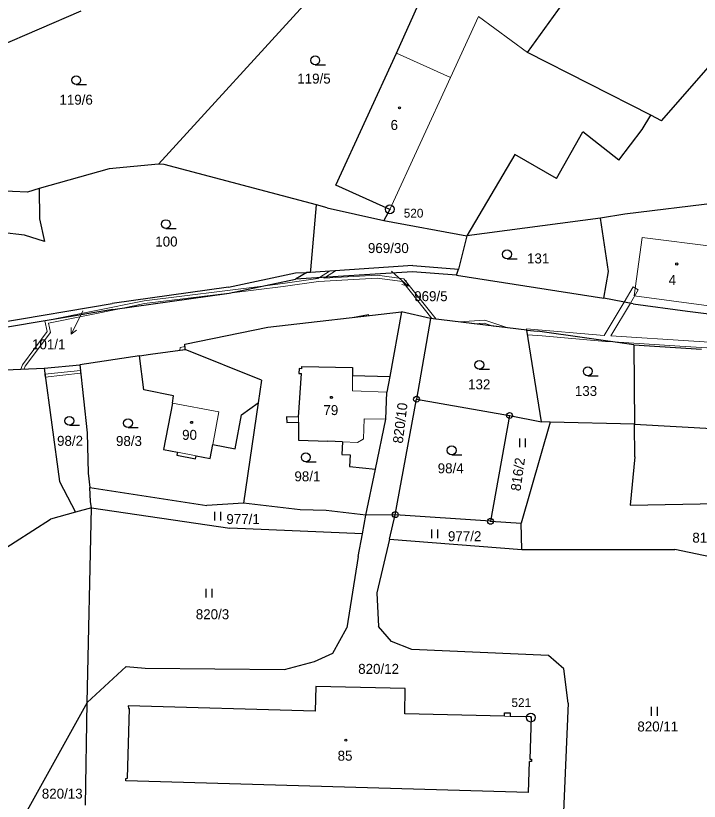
# Model space of a CAD drawing. Extents: x -754970 to -752637, y -970569 to -968179.
# Drawn here: x -752908.8 to -752792.3, y -969522.6 to -969388.8 of the extents above; entities that cross this region are included whole.
import ezdxf
from ezdxf.enums import TextEntityAlignment as Align

# ---------------------------------------------------------------- set-up
doc = ezdxf.new("R2010")
doc.units = 0
doc.header["$LTSCALE"] = 0.68
for name, color, linetype, lineweight in [('1', 7, 'Continuous', 25), ('13', 7, 'Continuous', 13), ('3', 7, 'Continuous', 25), ('4', 7, 'Continuous', 13), ('5', 7, 'Continuous', 25), ('7', 7, 'Continuous', 13), ('8', 7, 'Continuous', 25)]:
    doc.layers.add(name, color=color, linetype=linetype, lineweight=lineweight)
doc.layers.add('2', color=7, linetype='Continuous')

msp = doc.modelspace()

# ---------------------------------------------------------------- linework, layer by layer
at = {"layer": '1'}
for p, q in [((-752884.46, -969414.09), (-752849.18, -969375.41)), ((-752798.77, -969406.66), (-752773.21, -969377.55)), ((-752843.92, -969395.16), (-752838.37, -969382.79)), ((-752821.57, -969395.02), (-752815.7, -969386.84)), ((-752897.67, -969387.98), (-752916.6, -969396.15)), ((-752800.58, -969405.74), (-752821.57, -969395.02)), ((-752854.25, -969417.65), (-752843.92, -969395.16)), ((-752802.06, -969408.16), (-752800.58, -969405.74)), ((-752798.77, -969406.66), (-752800.58, -969405.74)), ((-752806.02, -969413.38), (-752802.06, -969408.16)), ((-752816.62, -969416.52), (-752812.14, -969408.53)), ((-752806.02, -969413.38), (-752812.14, -969408.53)), ((-752823.72, -969412.4), (-752831.91, -969426.26)), ((-752816.62, -969416.52), (-752823.72, -969412.4)), ((-752892.83, -969414.85), (-752904.76, -969418.2)), ((-752884.46, -969414.09), (-752892.83, -969414.85)), ((-752883.49, -969414.15), (-752884.46, -969414.09)), ((-752857.54, -969421.01), (-752883.49, -969414.15)), ((-752845.04, -969421.78), (-752854.25, -969417.65)), ((-752906.77, -969418.85), (-752915.73, -969418.39)), ((-752904.76, -969418.2), (-752906.77, -969418.85)), ((-752904.76, -969418.2), (-752904.73, -969423.36)), ((-752855.73, -969421.49), (-752857.54, -969421.01)), ((-752855.73, -969421.49), (-752846.06, -969423.68)), ((-752845.04, -969421.78), (-752846.06, -969423.68)), ((-752788.87, -969420.63), (-752805.01, -969422.57)), ((-752805.01, -969422.57), (-752809.16, -969423.27)), ((-752904.73, -969423.36), (-752903.86, -969427.22)), ((-752846.06, -969423.68), (-752831.91, -969426.26)), ((-752809.16, -969423.27), (-752831.91, -969426.26)), ((-752807.79, -969432.34), (-752809.16, -969423.27)), ((-752907.26, -969426.14), (-752911.21, -969425.74)), ((-752903.86, -969427.22), (-752907.26, -969426.14)), ((-752831.91, -969426.26), (-752833.34, -969431.94)), ((-752841.18, -969432.44), (-752861.1, -969433.64)), ((-752858.58, -969432.51), (-752859.17, -969432.53)), ((-752841.1, -969431.35), (-752858.58, -969432.51)), ((-752833.66, -969432.96), (-752841.18, -969432.44)), ((-752841.1, -969431.35), (-752833.34, -969431.94)), ((-752833.66, -969432.96), (-752833.34, -969431.94)), ((-752808.57, -969436.9), (-752807.79, -969432.34)), ((-752872.52, -969435.04), (-752861.12, -969432.61)), ((-752872.39, -969436.03), (-752861.1, -969433.64)), ((-752861.12, -969432.61), (-752859.17, -969432.53)), ((-752859.17, -969432.53), (-752861.1, -969433.64)), ((-752833.66, -969432.96), (-752808.57, -969436.9)), ((-752872.52, -969435.04), (-752892.34, -969437.83)), ((-752892.24, -969438.82), (-752872.39, -969436.03)), ((-752913.32, -969441.36), (-752892.34, -969437.83)), ((-752803.56, -969437.86), (-752808.57, -969436.9)), ((-752803.56, -969437.86), (-752794.35, -969439.13)), ((-752892.24, -969438.82), (-752913.29, -969442.36)), ((-752794.35, -969439.13), (-752790.7, -969439.55)), ((-752865.83, -969441.83), (-752843.03, -969439.23)), ((-752843.03, -969439.23), (-752845.05, -969450.28)), ((-752838.11, -969440.34), (-752843.03, -969439.23)), ((-752838.11, -969440.34), (-752840.49, -969454.12)), ((-752821.68, -969442.38), (-752838.11, -969440.34)), ((-752879.95, -969444.75), (-752865.83, -969441.83)), ((-752821.68, -969442.38), (-752819.87, -969442.54)), ((-752819.2, -969457.99), (-752821.68, -969442.38)), ((-752803.45, -969444.83), (-752819.87, -969442.54)), ((-752885.8, -969446.43), (-752879.88, -969445.64)), ((-752879.88, -969445.64), (-752879.95, -969444.75)), ((-752866.91, -969450.87), (-752879.88, -969445.64)), ((-752803.45, -969444.83), (-752803.36, -969458.4)), ((-752803.45, -969444.83), (-752791.94, -969445.58)), ((-752887.67, -969446.72), (-752897.86, -969448.27)), ((-752887.67, -969446.72), (-752885.8, -969446.43)), ((-752886.96, -969452.54), (-752887.67, -969446.72)), ((-752903.95, -969448.82), (-752897.86, -969448.27)), ((-752897.86, -969448.27), (-752896.62, -969459.86)), ((-752860.05, -969448.93), (-752860.02, -969448.52)), ((-752860.02, -969448.52), (-752851.38, -969448.74)), ((-752932.04, -969449.98), (-752903.95, -969448.82)), ((-752903.95, -969448.82), (-752901.3, -969468.17)), ((-752860.57, -969457.18), (-752860.1, -969449.76)), ((-752860.48, -969448.89), (-752860.53, -969449.72)), ((-752860.53, -969449.72), (-752860.1, -969449.76)), ((-752860.05, -969448.93), (-752860.48, -969448.89)), ((-752851.38, -969448.74), (-752851.39, -969450.1)), ((-752866.91, -969450.87), (-752867.47, -969454.74)), ((-752851.39, -969450.1), (-752845.05, -969450.28)), ((-752845.05, -969450.28), (-752845.53, -969452.93)), ((-752881.87, -969453.52), (-752886.96, -969452.54)), ((-752882.04, -969454.79), (-752881.87, -969453.52)), ((-752845.71, -969457.55), (-752845.53, -969452.93)), ((-752882.04, -969454.79), (-752883.57, -969462.68)), ((-752870.3, -969456.78), (-752867.47, -969454.74)), ((-752867.47, -969454.74), (-752869.95, -969471.81)), ((-752844.11, -969473.8), (-752840.49, -969454.12)), ((-752840.49, -969454.12), (-752824.64, -969456.91)), ((-752871.4, -969462.57), (-752870.3, -969456.78)), ((-752862.64, -969457.12), (-752862.61, -969458.07)), ((-752860.57, -969457.18), (-752862.64, -969457.12)), ((-752847.47, -969466.06), (-752845.71, -969457.55)), ((-752824.64, -969456.91), (-752827.89, -969474.93)), ((-752824.64, -969456.91), (-752819.2, -969457.99)), ((-752862.61, -969458.07), (-752860.57, -969458.05)), ((-752860.57, -969458.05), (-752860.62, -969461.12)), ((-752817.72, -969458.03), (-752822.69, -969475.24)), ((-752817.72, -969458.03), (-752819.2, -969457.99)), ((-752803.36, -969458.4), (-752817.72, -969458.03)), ((-752803.36, -969458.4), (-752772, -969460.14)), ((-752803.28, -969463.92), (-752803.36, -969458.4)), ((-752896.62, -969459.86), (-752896.45, -969466.73)), ((-752875.67, -969464.23), (-752875.21, -969461.84)), ((-752875.21, -969461.84), (-752871.4, -969462.57)), ((-752860.62, -969461.12), (-752855.61, -969461.29)), ((-752853.13, -969461.37), (-752855.61, -969461.29)), ((-752853.13, -969461.37), (-752853.23, -969463.53)), ((-752883.57, -969462.68), (-752881.21, -969463.14)), ((-752881.21, -969463.14), (-752881.3, -969463.65)), ((-752881.3, -969463.65), (-752878.15, -969464.26)), ((-752878.15, -969464.26), (-752878.06, -969463.76)), ((-752878.06, -969463.76), (-752875.67, -969464.23)), ((-752853.23, -969463.53), (-752851.77, -969463.6)), ((-752851.77, -969463.6), (-752851.92, -969465.57)), ((-752803.28, -969463.92), (-752804.12, -969472.17)), ((-752851.92, -969465.57), (-752847.47, -969466.06)), ((-752896.45, -969466.73), (-752896.17, -969469.17)), ((-752849.1, -969473.89), (-752847.47, -969466.06)), ((-752901.3, -969468.17), (-752898.58, -969473.38)), ((-752896.01, -969471.57), (-752896.17, -969469.17)), ((-752896.17, -969469.17), (-752876.22, -969472.26)), ((-752804.12, -969472.17), (-752747.83, -969471.17)), ((-752895.87, -969472.63), (-752898.58, -969473.38)), ((-752896.58, -969505.8), (-752895.87, -969472.63)), ((-752895.87, -969472.63), (-752896.01, -969471.57)), ((-752895.87, -969472.63), (-752872.3, -969476.08)), ((-752869.95, -969471.81), (-752876.22, -969472.26)), ((-752860.34, -969472.98), (-752869.95, -969471.81)), ((-752898.58, -969473.38), (-752902.85, -969474.55)), ((-752855.9, -969473.11), (-752860.34, -969472.98)), ((-752849.1, -969473.89), (-752855.9, -969473.11)), ((-752849.7, -969477.08), (-752849.1, -969473.89)), ((-752844.11, -969473.8), (-752849.1, -969473.89)), ((-752845.09, -969477.97), (-752844.11, -969473.8)), ((-752827.89, -969474.93), (-752844.11, -969473.8)), ((-752926.34, -969489.6), (-752902.85, -969474.55)), ((-752827.89, -969474.93), (-752822.69, -969475.24)), ((-752822.53, -969479.74), (-752822.69, -969475.24)), ((-752849.7, -969477.08), (-752872.3, -969476.08)), ((-752850.42, -969480.91), (-752849.7, -969477.08)), ((-752845.09, -969477.97), (-752847.26, -969487.14)), ((-752845.09, -969477.97), (-752822.53, -969479.74)), ((-752822.53, -969479.74), (-752796.46, -969479.74)), ((-752777.3, -969483.83), (-752796.46, -969479.74)), ((-752850.42, -969480.91), (-752852.35, -969493.06)), ((-752847.26, -969487.14), (-752846.98, -969492.87)), ((-752854.77, -969497.39), (-752852.35, -969493.06)), ((-752844.74, -969495.41), (-752846.98, -969492.87)), ((-752841.28, -969496.75), (-752844.74, -969495.41)), ((-752818.01, -969497.8), (-752841.28, -969496.75)), ((-752857.87, -969498.84), (-752854.77, -969497.39)), ((-752815.41, -969500.09), (-752818.01, -969497.8)), ((-752863.01, -969500.17), (-752857.87, -969498.84)), ((-752896.58, -969505.8), (-752889.93, -969499.68)), ((-752889.93, -969499.68), (-752886.71, -969499.94)), ((-752886.71, -969499.94), (-752863.01, -969500.17)), ((-752814.64, -969505.92), (-752815.41, -969500.09)), ((-752857.67, -969503.08), (-752857.77, -969507.31)), ((-752842.44, -969503.42), (-752857.67, -969503.08)), ((-752842.49, -969507.76), (-752842.44, -969503.42)), ((-752896.58, -969505.8), (-752906.84, -969524.19)), ((-752896.86, -969523.29), (-752896.58, -969505.8)), ((-752814.64, -969505.92), (-752815.49, -969525.74)), ((-752889.73, -969518.72), (-752889.41, -969506.83)), ((-752857.77, -969507.31), (-752889.59, -969506.38)), ((-752889.59, -969506.38), (-752889.58, -969506.81)), ((-752889.58, -969506.81), (-752889.41, -969506.83)), ((-752825.5, -969508.16), (-752842.49, -969507.76)), ((-752825.5, -969508.16), (-752825.49, -969507.57)), ((-752825.49, -969507.57), (-752824.54, -969507.59)), ((-752824.54, -969507.59), (-752824.53, -969508.18)), ((-752820.95, -969508.27), (-752824.53, -969508.18)), ((-752820.95, -969508.27), (-752821.17, -969515.45)), ((-752821.17, -969515.45), (-752820.88, -969515.45)), ((-752820.88, -969515.45), (-752820.9, -969515.87)), ((-752821.43, -969521.16), (-752821.23, -969515.85)), ((-752820.9, -969515.87), (-752821.23, -969515.85)), ((-752890.01, -969519.18), (-752889.99, -969518.76)), ((-752821.43, -969521.16), (-752890.01, -969519.18)), ((-752889.99, -969518.76), (-752889.73, -969518.72))]:
    msp.add_line(p, q, dxfattribs=at)
msp.add_lwpolyline([(-752858.58, -969432.51), (-752858.49, -969432.1), (-752857.54, -969421.01)], dxfattribs=at)
at = {"layer": '13'}
for points in [[(-752855.34, -969432.3), (-752857.03, -969433.4), (-752856.02, -969433.33), (-752854.32, -969432.23)], [(-752856.27, -969433.49), (-752856.02, -969433.33), (-752857.03, -969433.4), (-752857.28, -969433.56), (-752863.25, -969434.4), (-752866.73, -969434.83), (-752872.39, -969436.03), (-752863.19, -969434.9), (-752857.17, -969434.05), (-752847.22, -969433.49), (-752842.89, -969434.06), (-752837.86, -969440.37), (-752837.15, -969440.46), (-752842.63, -969433.59), (-752847.2, -969432.99)], [(-752866.73, -969434.83), (-752886.91, -969437.33), (-752903.8, -969440.76), (-752892.24, -969438.82), (-752890.5, -969438.58), (-752886.83, -969437.83), (-752872.39, -969436.03)], [(-752803.57, -969434.99), (-752805.11, -969437.56), (-752804.06, -969437.76), (-752802.71, -969435.51)], [(-752821.68, -969442.38), (-752819.87, -969442.54), (-752806.91, -969444.35), (-752795.65, -969445.1), (-752785.47, -969445.72), (-752775.64, -969445.94), (-752754.03, -969444.74), (-752748.22, -969443.42), (-752779.11, -969445.13), (-752807.38, -969443.31), (-752804.06, -969437.76), (-752805.11, -969437.56), (-752808.5, -969443.24), (-752821.76, -969442.11), (-752821.72, -969442.37)], [(-752892.24, -969438.82), (-752903.8, -969440.76), (-752903.4, -969442.61), (-752907.64, -969448.25), (-752907.9, -969448.98), (-752907.36, -969448.96), (-752907.19, -969448.49), (-752902.86, -969442.73), (-752903.2, -969441.16), (-752890.5, -969438.58)], [(-752848.68, -969439.71), (-752851.41, -969440.19), (-752848.65, -969439.87)], [(-752833.31, -969440.94), (-752830.67, -969441.26), (-752828.94, -969441.15), (-752827.41, -969441.67), (-752824.95, -969441.97), (-752828.87, -969440.64)], [(-752821.56, -969443.13), (-752819.1, -969443.34), (-752808.27, -969444.26), (-752806.91, -969444.35), (-752819.87, -969442.54), (-752821.68, -969442.38)], [(-752879.88, -969445.64), (-752879.92, -969445.15), (-752880.78, -969445.3), (-752880.79, -969445.76)], [(-752897.76, -969449.22), (-752903.81, -969449.86), (-752903.74, -969450.36), (-752897.71, -969449.71)]]:
    msp.add_lwpolyline(points, close=True, dxfattribs=at)
at = {"layer": '3'}
for p, q in [((-752857.743, -969397.13), (-752855.993, -969397.13)), ((-752898.463, -969400.5), (-752896.713, -969400.5)), ((-752883.183, -969425.03), (-752881.433, -969425.03)), ((-752825.073, -969430.18), (-752823.323, -969430.18)), ((-752829.793, -969449.01), (-752828.043, -969449.01)), ((-752811.323, -969450.12), (-752809.573, -969450.12)), ((-752899.633, -969458.55), (-752897.883, -969458.55)), ((-752889.643, -969458.96), (-752887.893, -969458.96)), ((-752822.911, -969462.32), (-752822.911, -969460.82)), ((-752821.91, -969462.32), (-752821.91, -969460.82)), ((-752834.503, -969463.59), (-752832.753, -969463.59)), ((-752859.363, -969464.77), (-752857.613, -969464.77)), ((-752874.841, -969474.81), (-752874.841, -969473.31)), ((-752873.84, -969474.81), (-752873.84, -969473.31)), ((-752837.861, -969477.81), (-752837.861, -969476.31)), ((-752836.86, -969477.81), (-752836.86, -969476.31)), ((-752876.301, -969487.94), (-752876.301, -969486.44)), ((-752875.3, -969487.94), (-752875.3, -969486.44)), ((-752800.451, -969508.06), (-752800.451, -969506.56)), ((-752799.45, -969508.06), (-752799.45, -969506.56))]:
    msp.add_line(p, q, dxfattribs=at)
for centre in [(-752857.7429, -969396.3798), (-752898.4629, -969399.7498), (-752883.1829, -969424.2798), (-752825.0729, -969429.4298), (-752829.7929, -969448.2598), (-752811.3229, -969449.3698), (-752899.6329, -969457.7998), (-752889.6429, -969458.2098), (-752859.3629, -969464.0198), (-752834.5029, -969462.8398)]:
    msp.add_circle(centre, 0.75, dxfattribs=at)
at = {"layer": '4'}
for p, q in [((-752829.92, -969388.93), (-752834.69, -969399.32)), ((-752821.57, -969395.02), (-752829.92, -969388.93)), ((-752843.92, -969395.16), (-752834.69, -969399.32)), ((-752834.69, -969399.32), (-752845.04, -969421.78)), ((-752803.42, -969436.53), (-752802.04, -969426.55)), ((-752802.04, -969426.55), (-752789.39, -969428.18)), ((-752803.42, -969436.53), (-752790.69, -969438.22)), ((-752851.39, -969450.1), (-752851.41, -969452.71)), ((-752845.53, -969452.93), (-752851.41, -969452.71)), ((-752874.15, -969456.3), (-752882.04, -969454.79)), ((-752875.21, -969461.84), (-752874.15, -969456.3)), ((-752860.57, -969457.18), (-752860.57, -969458.05)), ((-752881.21, -969463.14), (-752878.06, -969463.76)), ((-752824.53, -969508.18), (-752825.5, -969508.16))]:
    msp.add_line(p, q, dxfattribs=at)
for points in [[(-752849.56, -969460.95), (-752849.5, -969460.86), (-752849.4, -969457.45), (-752845.71, -969457.55)], [(-752853.13, -969461.37), (-752850.54, -969461.5), (-752849.56, -969460.95)]]:
    msp.add_lwpolyline(points, dxfattribs=at)
at = {"layer": '5'}
for centre in [(-752843.3968, -969404.4692), (-752796.1668, -969431.0792), (-752854.9968, -969453.8092), (-752878.8068, -969458.0692), (-752852.5168, -969512.2192)]:
    msp.add_circle(centre, 0.175, dxfattribs=at)
at = {"layer": '7'}
for p, q in [((-752841.89, -969434.858), (-752842.299, -969433.816)), ((-752899.332, -969443.044), (-752898.432, -969442.379))]:
    msp.add_line(p, q, dxfattribs=at)
for points in [[(-752844.76, -969432.28), (-752844.12, -969432.85), (-752841.89, -969434.858), (-752842.969, -969434.56)], [(-752897.32, -969439.06), (-752897.97, -969440.37), (-752899.332, -969443.044), (-752899.324, -969441.924)]]:
    msp.add_lwpolyline(points, dxfattribs=at)
at = {"layer": '8'}
for centre, radius in [((-752845.03, -969421.7598), 0.75), ((-752845.03, -969421.7598), 0.03), ((-752840.49, -969454.1199), 0.5), ((-752840.49, -969454.1199), 0.0303), ((-752824.64, -969456.9099), 0.5), ((-752824.64, -969456.9099), 0.0303), ((-752844.11, -969473.7999), 0.5), ((-752844.11, -969473.7999), 0.0303), ((-752827.89, -969474.9299), 0.5), ((-752827.89, -969474.9299), 0.0303), ((-752821.02, -969508.3798), 0.75), ((-752821.02, -969508.3798), 0.03)]:
    msp.add_circle(centre, radius, dxfattribs=at)

# ---------------------------------------------------------------- texts
at = {"layer": '2'}
for s, p in [('119/5', (-752857.96, -969400.335)), ('119/6', (-752898.48, -969403.935)), ('6', (-752844.28, -969408.235)), ('100', (-752883.099, -969428.105)), ('969/30', (-752845.29, -969429.215)), ('131', (-752819.769, -969430.985)), ('4', (-752796.91, -969434.655)), ('132', (-752829.809, -969452.435)), ('133', (-752811.619, -969453.565)), ('79', (-752855.089, -969456.825)), ('98/2', (-752899.519, -969462.065)), ('98/3', (-752889.479, -969462.095)), ('90', (-752879.159, -969461.045)), ('98/4', (-752834.669, -969466.745)), ('98/1', (-752859.079, -969468.115)), ('977/1', (-752870.04, -969475.395)), ('977/2', (-752832.29, -969478.315)), ('816/3', (-752790.66, -969478.565)), ('820/3', (-752875.25, -969491.615)), ('820/12', (-752846.95, -969500.925)), ('820/11', (-752799.39, -969510.745)), ('85', (-752852.669, -969515.725)), ('820/13', (-752900.85, -969522.185))]:
    msp.add_text(s, height=1.7, dxfattribs=at).set_placement(p, align=Align.CENTER)
msp.add_text('969/5', height=1.7, dxfattribs=at).set_placement((-752840.89, -969437.415))
msp.add_text('101/1', height=1.7, dxfattribs=at).set_placement((-752900.31, -969445.615), align=Align.RIGHT)
for s, rotation, p in [('820/10', 83, (-752842.4311, -969458.2891)), ('816/2', 82, (-752822.3898, -969467.0383))]:
    msp.add_text(s, height=1.7, rotation=rotation, dxfattribs=at).set_placement(p, align=Align.CENTER)
at = {"layer": '8'}
for s, p in [('520', (-752839.319, -969423.169)), ('521', (-752820.972, -969506.576))]:
    msp.add_text(s, height=1.5, dxfattribs=at).set_placement(p, align=Align.RIGHT)

doc.saveas('drawing.dxf')
